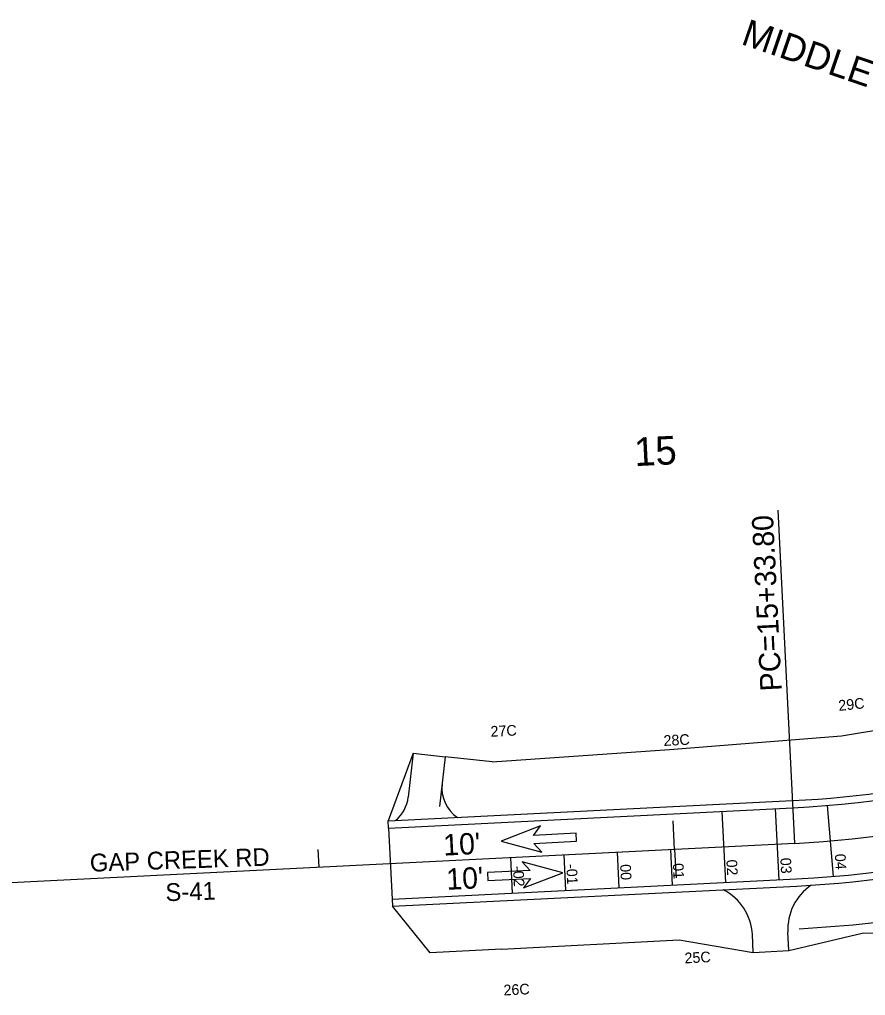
# Model space of a CAD drawing. Extents: x 126 to 1541327, y 13613 to 1200627.
# Drawn here: x 1539708.9 to 1539946.5, y 1199334.3 to 1199608.4 of the extents above; entities that cross this region are included whole.
import ezdxf

# ---------------------------------------------------------------- set-up
doc = ezdxf.new("R2010")
doc.units = 0
for name, color, linetype in [('RD_EX_Road Text', 7, 'Continuous'), ('RD_HC_Cl', 7, 'Continuous'), ('RD_HC_Data', 7, 'Continuous'), ('RD_HC_Data_Tic', 7, 'Continuous'), ('RD_HC_TX_Sta50', 7, 'Continuous'), ('RD_PD_ALT1_TX', 7, 'Continuous'), ('RD_PD_CstnLmt', 7, 'Continuous'), ('RD_PD_CstnLmt_TX', 7, 'Continuous'), ('RD_PD_Driveway', 7, 'Continuous'), ('RD_PD_Final_TrvlWay', 7, 'Continuous'), ('RD_PD_Final_TX', 7, 'Continuous'), ('RD_PD_PaveShd', 7, 'Continuous'), ('RD_Sketch8', 7, 'Continuous')]:
    doc.layers.add(name, color=color, linetype=linetype)

msp = doc.modelspace()

# ---------------------------------------------------------------- linework, layer by layer
at = {"layer": 'RD_HC_Cl'}
msp.add_line((1539393.53, 1199350.4), (1539926.66, 1199377.06), dxfattribs=at)
msp.add_arc((1539911.68, 1199676.68), 300, 272.8619, 321.687, dxfattribs=at)
at = {"layer": 'RD_HC_Data'}
msp.add_line((1539926.66, 1199377.06), (1539921.99, 1199470.56), dxfattribs=at)
at = {"layer": 'RD_HC_Data_Tic'}
for p, q in [((1539892.91, 1199375.37), (1539892.51, 1199383.36)), ((1539793.03, 1199370.38), (1539792.78, 1199375.37)), ((1539892.91, 1199375.37), (1539893.31, 1199367.38))]:
    msp.add_line(p, q, dxfattribs=at)
at = {"layer": 'RD_PD_ALT1_TX'}
for p, q in [((1539906.19, 1199386.04), (1539907.19, 1199366.07)), ((1539921.17, 1199386.79), (1539922.17, 1199366.82)), ((1539935.81, 1199387.69), (1539937.47, 1199367.76)), ((1539891.71, 1199375.31), (1539892.21, 1199365.32)), ((1539846.76, 1199373.06), (1539847.26, 1199363.07)), ((1539861.74, 1199373.81), (1539862.24, 1199363.82)), ((1539876.73, 1199374.56), (1539877.22, 1199364.57))]:
    msp.add_line(p, q, dxfattribs=at)
at = {"layer": 'RD_PD_CstnLmt'}
for p, q in [((1539939.79, 1199407.26), (1539984.44, 1199414.44)), ((1539891.5, 1199403.41), (1539939.79, 1199407.26)), ((1539819.48, 1199402.39), (1539812.41, 1199383.36)), ((1539841.61, 1199399.97), (1539891.5, 1199403.41)), ((1539841.61, 1199399.97), (1539828.45, 1199401.37)), ((1539824.27, 1199346.31), (1539813.61, 1199359.39)), ((1539844.25, 1199347.31), (1539894.18, 1199349.95)), ((1539894.18, 1199349.95), (1539914.99, 1199346.44)), ((1539924.98, 1199346.93), (1539945.58, 1199351.83)), ((1539945.58, 1199351.83), (1539972.43, 1199352.28)), ((1539844.25, 1199347.31), (1539824.27, 1199346.31))]:
    msp.add_line(p, q, dxfattribs=at)
at = {"layer": 'RD_PD_Driveway'}
for p, q in [((1539819.48, 1199402.39), (1539818.07, 1199390.02)), ((1539819.48, 1199402.39), (1539828.45, 1199401.37)), ((1539828.45, 1199401.37), (1539826.86, 1199387.43)), ((1539914.99, 1199346.44), (1539914.75, 1199351.43)), ((1539924.98, 1199346.93), (1539924.72, 1199352.14)), ((1539914.99, 1199346.44), (1539924.98, 1199346.93))]:
    msp.add_line(p, q, dxfattribs=at)
for centre, radius, start, end in [((1539837.51, 1199392.62), 10, 173.4885, 235.992), ((1539808.13, 1199391.16), 10, 309.7318, 353.4885), ((1539899.76, 1199350.68), 15, 2.8619, 62.9354), ((1539939.7, 1199352.89), 15, 124.2058, 182.8619)]:
    msp.add_arc(centre, radius, start, end, dxfattribs=at)
at = {"layer": 'RD_PD_Final_TrvlWay'}
for p, q in [((1539812.51, 1199381.36), (1539926.16, 1199387.04)), ((1539812.51, 1199381.36), (1539813.51, 1199361.39)), ((1539813.51, 1199361.39), (1539927.16, 1199367.07))]:
    msp.add_line(p, q, dxfattribs=at)
for radius, end in [(290, 301.8034), (310, 301.6792)]:
    msp.add_arc((1539911.68, 1199676.68), radius, 272.8619, end, dxfattribs=at)
at = {"layer": 'RD_PD_Final_TX'}
for p, q in [((1539855.19, 1199381.93), (1539844.14, 1199377.7)), ((1539853.22, 1199379.28), (1539855.19, 1199381.93)), ((1539844.14, 1199377.7), (1539855.56, 1199374.59)), ((1539865.21, 1199379.88), (1539853.22, 1199379.28)), ((1539853.33, 1199377.03), (1539865.32, 1199377.63)), ((1539865.32, 1199377.63), (1539865.21, 1199379.88)), ((1539855.56, 1199374.59), (1539853.33, 1199377.03)), ((1539861.51, 1199368.79), (1539850.09, 1199371.9)), ((1539850.09, 1199371.9), (1539852.32, 1199369.45)), ((1539852.32, 1199369.45), (1539840.33, 1199368.86)), ((1539840.33, 1199368.86), (1539840.44, 1199366.61)), ((1539840.44, 1199366.61), (1539852.43, 1199367.21)), ((1539850.46, 1199364.56), (1539861.51, 1199368.79)), ((1539852.43, 1199367.21), (1539850.46, 1199364.56))]:
    msp.add_line(p, q, dxfattribs=at)
at = {"layer": 'RD_PD_PaveShd'}
for p, q in [((1539812.41, 1199383.36), (1539926.06, 1199389.04)), ((1539812.51, 1199381.36), (1539812.41, 1199383.36)), ((1539813.61, 1199359.39), (1539927.26, 1199365.07)), ((1539813.51, 1199361.39), (1539813.61, 1199359.39))]:
    msp.add_line(p, q, dxfattribs=at)
for radius, end in [(288, 295.5911), (312, 296.0265)]:
    msp.add_arc((1539911.68, 1199676.68), radius, 272.8619, end, dxfattribs=at)
at = {"layer": 'RD_Sketch8'}
msp.add_arc((1539911.68, 1199676.68), 324, 272.8619, 301.5493, dxfattribs=at)

# ---------------------------------------------------------------- texts
at = {"layer": 'RD_EX_Road Text'}
for s, rotation, p in [('GAP CREEK RD', 1.961, (1539728.7, 1199369.07)), ('S-41', 1.8839, (1539749.94, 1199360.8))]:
    msp.add_text(s, height=5, rotation=rotation, dxfattribs=at).set_placement(p)
at = {"layer": 'RD_HC_Data'}
for s, height, rotation, p in [('MIDDLE SALUDA RIVER', 7.5, 341.1022, (1539911.29, 1199601.54)), ('PC=15+33.80', 6, 92.8619, (1539923.02, 1199419.91))]:
    msp.add_text(s, height=height, rotation=rotation, dxfattribs=at).set_placement(p)
at = {"layer": 'RD_HC_TX_Sta50'}
msp.add_text('15', height=8, rotation=2.8619, dxfattribs=at).set_placement((1539881.76, 1199482.95))
at = {"layer": 'RD_PD_ALT1_TX'}
for s, p in [('02', (1539907.45, 1199372.42)), ('03', (1539922.6, 1199372.93)), ('04', (1539937.92, 1199374.04)), ('-02', (1539847.47, 1199370.61)), ('-01', (1539862.46, 1199371.18)), ('00', (1539877.59, 1199371.12)), ('01', (1539892.4, 1199371.41))]:
    msp.add_text(s, height=3, rotation=272.8619, dxfattribs=at).set_placement(p)
at = {"layer": 'RD_PD_CstnLmt_TX'}
for s, rotation, p in [('29C', 5.9561, (1539939.07, 1199414.22)), ('27C', 2.8619, (1539841.26, 1199406.97)), ('28C', 2.8619, (1539889.86, 1199404.39)), ('25C', 2.8619, (1539895.76, 1199343.34)), ('26C', 2.8619, (1539844.9, 1199334.33))]:
    msp.add_text(s, height=3, rotation=rotation, dxfattribs=at).set_placement(p)
at = {"layer": 'RD_PD_Final_TX'}
for p in [(1539828.03, 1199373.59), (1539828.89, 1199363.98)]:
    msp.add_text("10'", height=6, rotation=2.862, dxfattribs=at).set_placement(p)

doc.saveas('drawing.dxf')
